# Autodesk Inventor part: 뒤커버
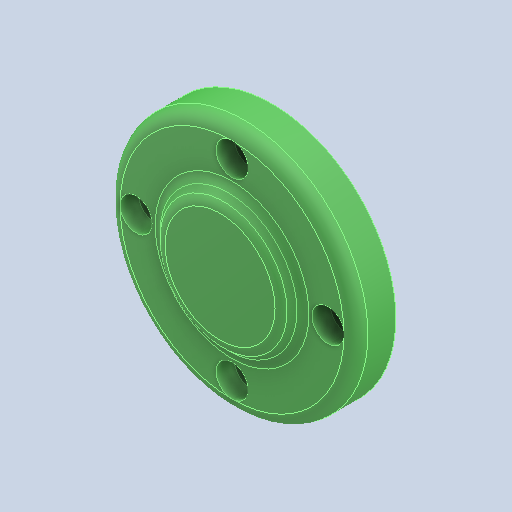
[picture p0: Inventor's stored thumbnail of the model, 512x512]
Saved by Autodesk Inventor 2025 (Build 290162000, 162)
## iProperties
Created: 2024-07
Part Number: 뒤커버
Material: 알루미늄 6061
Document SubType Name: Modeling
Designer: parkm
Density: 2.71 g/cm^3
Appearance: 기본값
Author: jhkim
Sending System: Autodesk Inventor 2025
Preprocessor: ST-DEVELOPER v20
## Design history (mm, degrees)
feature "솔리드1"
node "솔리드2"
